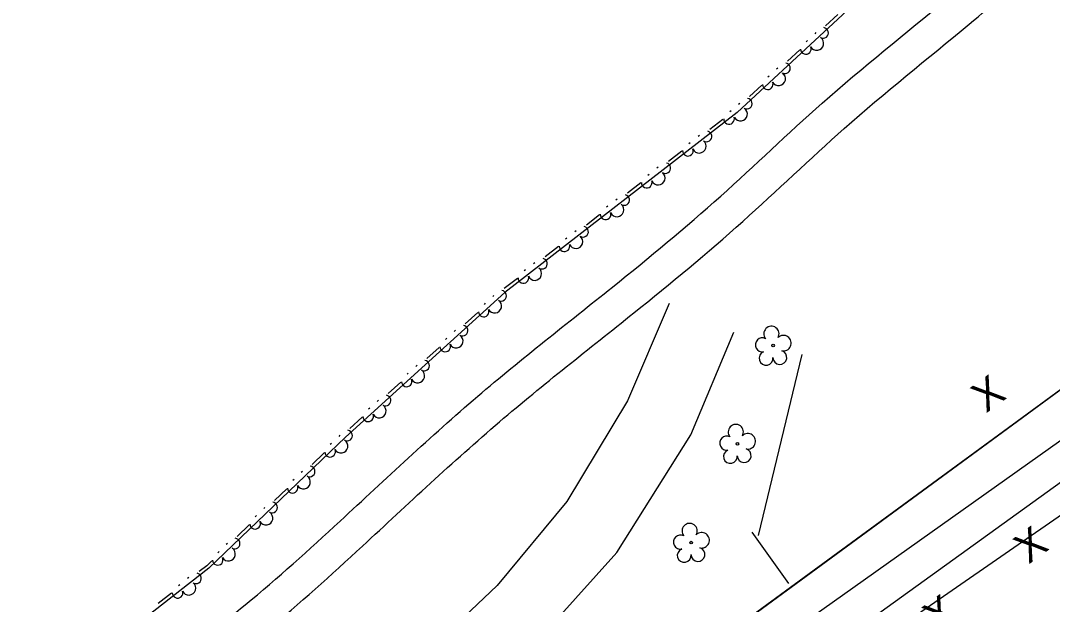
# Model space of a CAD drawing. Extents: x 1577032 to 1581865, y 611492 to 615011.
# Drawn here: x 1580788.7 to 1581041, y 614245.5 to 614388.2 of the extents above; entities that cross this region are included whole.
import ezdxf

# ---------------------------------------------------------------- set-up
doc = ezdxf.new("R2010")
doc.units = 0
for name, color, linetype in [('Exist Other Culture Fence Line', 7, 'Continuous'), ('Exist Right of Way Line', 7, 'Continuous'), ('Exist Roads Soil', 7, 'Continuous'), ('Exist Utilities Telephone UG FO SUE LOS B', 7, 'Continuous'), ('Exist Utilities Water UG Line SUE LOS B', 7, 'Continuous'), ('Exist Vegetation Tree CELL', 7, 'Continuous'), ('Old_Level_11', 7, 'Continuous'), ('Scratch_Level_4', 7, 'Continuous')]:
    doc.layers.add(name, color=color, linetype=linetype)

msp = doc.modelspace()

# ---------------------------------------------------------------- linework, layer by layer
at = {"layer": 'Exist Other Culture Fence Line'}
for p, q in [((1580969.09, 614262.33), (1580979.76, 614306.58)), ((1580969.09, 614262.33), (1580979.76, 614306.58)), ((1580976.57, 614250.53), (1580967.6, 614263.11)), ((1580976.57, 614250.53), (1580967.6, 614263.11))]:
    msp.add_line(p, q, dxfattribs=at)
for points in [[(1580843.54, 614151.95), (1580914.31, 614203.63), (1580981.96, 614253.3), (1581053.56, 614305.78), (1581115.1, 614350.96), (1581178.97, 614397.65), (1581213.26, 614422.92), (1581213.95, 614443.21), (1581207.27, 614448.89), (1581139.47, 614504.86)], [(1580843.54, 614151.95), (1581213.26, 614422.92), (1581213.95, 614443.21), (1581207.27, 614448.89), (1581139.47, 614504.86)], [(1580843.54, 614151.95), (1580914.31, 614203.63), (1580981.96, 614253.3), (1581053.56, 614305.78), (1581115.1, 614350.96), (1581178.97, 614397.65), (1581213.26, 614422.92), (1581213.95, 614443.21), (1581207.27, 614448.89)]]:
    msp.add_lwpolyline(points, dxfattribs=at)
at = {"layer": 'Exist Right of Way Line'}
msp.add_lwpolyline([(1580350.49, 613793.9), (1581560.23, 614652.99)], dxfattribs=at)
at = {"layer": 'Exist Roads Soil'}
for points in [[(1580947.25, 614319.05), (1580937.11, 614295.28), (1580922.28, 614270.62), (1580905.22, 614250.08), (1580885.95, 614231.74), (1580859.86, 614211.65), (1580836.93, 614193.69), (1580817.4, 614174.23), (1580801.52, 614151.03), (1580795.8, 614133.68), (1580792.46, 614114.3), (1580794.72, 614096.94), (1580801.59, 614080.9), (1580804.43, 614074.94), (1580805.4, 614069.46)], [(1580947.25, 614319.05), (1580937.11, 614295.28), (1580922.28, 614270.62), (1580905.22, 614250.08), (1580885.95, 614231.74), (1580859.86, 614211.65), (1580836.93, 614193.69), (1580817.4, 614174.23), (1580801.52, 614151.03), (1580795.8, 614133.68), (1580792.46, 614114.3), (1580794.72, 614096.94), (1580801.59, 614080.9), (1580804.43, 614074.94), (1580805.4, 614069.46)], [(1580842.62, 614097.61), (1580834.78, 614104.9), (1580827.64, 614117.28), (1580827.01, 614130.94), (1580831.8, 614152.77), (1580846.82, 614176.16), (1580880.36, 614204.32), (1580909.22, 614230.04), (1580934.52, 614258.19), (1580952.56, 614286.96), (1580963.08, 614312)], [(1580842.62, 614097.61), (1580834.78, 614104.9), (1580827.64, 614117.28), (1580827.01, 614130.94), (1580831.8, 614152.77), (1580846.82, 614176.16), (1580880.36, 614204.32), (1580909.22, 614230.04), (1580934.52, 614258.19), (1580952.56, 614286.96), (1580963.08, 614312)]]:
    msp.add_lwpolyline(points, dxfattribs=at)
at = {"layer": 'Exist Utilities Telephone UG FO SUE LOS B'}
msp.add_lwpolyline([(1580541.92, 613911.34), (1580565.99, 613928.5), (1580575.38, 613936.54), (1580607.26, 613958.8), (1580640.94, 613978.44), (1580673.15, 613998.31), (1580719.17, 614030.82), (1580788.35, 614087.85), (1580845.17, 614134.91), (1580876.01, 614149.96), (1580927.93, 614187.6), (1580984.72, 614225.98), (1580987.35, 614228.77), (1581072.57, 614287.71), (1581106.01, 614311.08), (1581124.14, 614323.41), (1581136.77, 614334.4), (1581140.56, 614340.68), (1581160.35, 614356.31), (1581239.56, 614412.21)], dxfattribs=at)
at = {"layer": 'Exist Utilities Water UG Line SUE LOS B'}
msp.add_line((1580981.18, 614230.87), (1581064.77, 614291.07), dxfattribs=at)
at = {"layer": 'Exist Vegetation Tree CELL'}
for p, q in [((1580972.67, 614308.76), (1580972.67, 614308.76)), ((1580963.95, 614284.75), (1580963.95, 614284.75)), ((1580952.67, 614260.56), (1580952.67, 614260.56))]:
    msp.add_line(p, q, dxfattribs=at)
for centre in [(1580972.67, 614308.76), (1580963.95, 614284.75), (1580952.67, 614260.56)]:
    msp.add_circle(centre, 0.326, dxfattribs=at)
for centre, radius, start, end in [((1580972.28, 614311.63), 1.86, 330.1651, 219.7134), ((1580970.06, 614308.91), 1.73, 62.6636, 279.3457), ((1580975.22, 614309.35), 1.9, 257.1011, 134.1999), ((1580970.96, 614305.64), 1.69, 111.5671, 6.231), ((1580974.34, 614305.86), 1.7, 181.2822, 74.56), ((1580963.57, 614287.63), 1.86, 330.1651, 219.7134), ((1580961.35, 614284.91), 1.73, 62.6636, 279.3457), ((1580966.5, 614285.34), 1.9, 257.1011, 134.1999), ((1580962.25, 614281.63), 1.69, 111.5671, 6.231), ((1580965.62, 614281.85), 1.7, 181.2822, 74.56), ((1580952.28, 614263.43), 1.86, 330.1651, 219.7134), ((1580950.06, 614260.71), 1.73, 62.6636, 279.3457), ((1580955.22, 614261.15), 1.9, 257.1011, 134.1999), ((1580950.96, 614257.44), 1.69, 111.5671, 6.231), ((1580954.34, 614257.66), 1.7, 181.2822, 74.56)]:
    msp.add_arc(centre, radius, start, end, dxfattribs=at)
at = {"layer": 'Old_Level_11'}
for points in [[(1581076.08, 614559.89), (1581088.52, 614547.83), (1581100.64, 614534.14), (1581112.37, 614518.46), (1581110.88, 614504.93), (1581098.08, 614486.05), (1581066.09, 614457.4), (1581031.44, 614426.4), (1580993.03, 614392.77), (1580963.93, 614365.74), (1580907.09, 614321.77), (1580868.13, 614286.39), (1580834.77, 614254.31), (1580805.23, 614231.21)], [(1580988.55, 614389.73), (1580985.54, 614386.94)], [(1580983.16, 614385.29), (1580982.86, 614385.01)], [(1580981.06, 614383.33), (1580980.76, 614383.06)], [(1580979.23, 614381.08), (1580976.23, 614378.29)], [(1580973.85, 614376.64), (1580973.55, 614376.36)], [(1580969.92, 614372.43), (1580966.91, 614369.64)], [(1580971.74, 614374.68), (1580971.44, 614374.4)], [(1580964.53, 614367.98), (1580964.23, 614367.7)], [(1580962.46, 614366.16), (1580962.14, 614365.91)], [(1580960.44, 614364.08), (1580957.2, 614361.57)], [(1580954.67, 614360.14), (1580954.35, 614359.89)], [(1580952.4, 614358.38), (1580952.08, 614358.13)], [(1580950.38, 614356.3), (1580947.14, 614353.79)], [(1580944.62, 614352.36), (1580944.3, 614352.11)], [(1580942.35, 614350.61), (1580942.03, 614350.36)], [(1580940.33, 614348.52), (1580937.09, 614346.02)], [(1580934.56, 614344.58), (1580934.24, 614344.33)], [(1580932.29, 614342.83), (1580931.97, 614342.58)], [(1580930.27, 614340.75), (1580927.03, 614338.24)], [(1580922.24, 614335.05), (1580921.91, 614334.8)], [(1580924.51, 614336.8), (1580924.18, 614336.55)], [(1580920.22, 614332.97), (1580916.97, 614330.46)], [(1580912.18, 614327.27), (1580911.86, 614327.02)], [(1580914.45, 614329.02), (1580914.13, 614328.77)], [(1580910.16, 614325.19), (1580906.92, 614322.68)], [(1580904.45, 614321.03), (1580904.14, 614320.76)], [(1580900.47, 614316.87), (1580897.44, 614314.11)], [(1580902.32, 614319.1), (1580902.02, 614318.83)], [(1580895.04, 614312.49), (1580894.73, 614312.21)], [(1580892.91, 614310.56), (1580892.61, 614310.28)], [(1580891.06, 614308.32), (1580888.03, 614305.57)], [(1580883.5, 614302.01), (1580883.2, 614301.73)], [(1580885.63, 614303.94), (1580885.32, 614303.66)], [(1580881.65, 614299.78), (1580878.62, 614297.02)], [(1580876.21, 614295.39), (1580875.91, 614295.12)], [(1580874.09, 614293.46), (1580873.79, 614293.19)], [(1580872.24, 614291.23), (1580869.2, 614288.47)], [(1580866.79, 614286.81), (1580866.5, 614286.52)], [(1580864.72, 614284.82), (1580864.43, 614284.53)], [(1580862.94, 614282.53), (1580859.98, 614279.69)], [(1580857.63, 614278), (1580857.33, 614277.71)], [(1580855.56, 614276.01), (1580855.26, 614275.72)], [(1580853.77, 614273.72), (1580850.81, 614270.88)], [(1580848.46, 614269.19), (1580848.17, 614268.9)], [(1580846.39, 614267.2), (1580846.1, 614266.91)], [(1580844.61, 614264.91), (1580841.65, 614262.07)], [(1580839.29, 614260.37), (1580839, 614260.09)], [(1580837.23, 614258.39), (1580836.93, 614258.1)], [(1580835.44, 614256.1), (1580834.23, 614254.93), (1580832.39, 614253.5)], [(1580829.88, 614252.05), (1580829.55, 614251.8)], [(1580827.61, 614250.28), (1580827.29, 614250.03)], [(1580825.61, 614248.19), (1580822.38, 614245.66)]]:
    msp.add_lwpolyline(points, dxfattribs=at)
for centre, radius, start, end in [((1580984.9, 614385.22), 1.3, 241.3186, 82.1152), ((1580983.36, 614382.67), 1.69, 208.8474, 56.9199), ((1580980.69, 614381.32), 1.3, 183.6522, 24.4487), ((1580975.59, 614376.57), 1.3, 241.3186, 82.1152), ((1580974.04, 614374.02), 1.69, 208.8474, 56.9199), ((1580971.38, 614372.66), 1.3, 183.6522, 24.4487), ((1580966.27, 614367.92), 1.3, 241.3186, 82.1152), ((1580964.72, 614365.37), 1.69, 208.8474, 56.9199), ((1580961.92, 614364.19), 1.3, 178.495, 19.2916), ((1580956.4, 614359.92), 1.3, 236.1615, 76.9581), ((1580954.63, 614357.52), 1.69, 203.6903, 51.7628), ((1580951.86, 614356.41), 1.3, 178.495, 19.2916), ((1580946.35, 614352.14), 1.3, 236.1615, 76.9581), ((1580944.58, 614349.74), 1.69, 203.6903, 51.7628), ((1580941.8, 614348.63), 1.3, 178.495, 19.2916), ((1580936.29, 614344.36), 1.3, 236.1615, 76.9581), ((1580934.52, 614341.96), 1.69, 203.6903, 51.7628), ((1580931.75, 614340.85), 1.3, 178.495, 19.2916), ((1580926.23, 614336.58), 1.3, 236.1615, 76.9581), ((1580924.47, 614334.18), 1.69, 203.6903, 51.7628), ((1580921.69, 614333.07), 1.3, 178.495, 19.2916), ((1580916.18, 614328.8), 1.3, 236.1615, 76.9581), ((1580914.41, 614326.4), 1.69, 203.6903, 51.7628), ((1580911.64, 614325.29), 1.3, 178.495, 19.2916), ((1580906.19, 614320.95), 1.3, 240.6812, 81.4778), ((1580904.61, 614318.41), 1.69, 208.21, 56.2825), ((1580901.94, 614317.09), 1.3, 183.0147, 23.8113), ((1580896.77, 614312.4), 1.3, 240.6812, 81.4778), ((1580895.2, 614309.87), 1.69, 208.21, 56.2825), ((1580892.52, 614308.54), 1.3, 183.0147, 23.8113), ((1580887.36, 614303.86), 1.3, 240.6812, 81.4778), ((1580885.79, 614301.32), 1.69, 208.21, 56.2825), ((1580883.11, 614300), 1.3, 183.0147, 23.8113), ((1580877.95, 614295.31), 1.3, 240.6812, 81.4778), ((1580876.38, 614292.77), 1.69, 208.21, 56.2825), ((1580873.7, 614291.45), 1.3, 183.0147, 23.8113), ((1580868.54, 614286.76), 1.3, 240.6812, 81.4778), ((1580867.03, 614284.19), 1.69, 209.8356, 57.9081), ((1580864.39, 614282.79), 1.3, 184.6403, 25.4369), ((1580859.37, 614277.96), 1.3, 242.3068, 83.1034), ((1580857.86, 614275.38), 1.69, 209.8356, 57.9081), ((1580855.23, 614273.98), 1.3, 184.6403, 25.4369), ((1580850.2, 614269.15), 1.3, 242.3068, 83.1034), ((1580848.7, 614266.57), 1.69, 209.8356, 57.9081), ((1580846.06, 614265.17), 1.3, 184.6403, 25.4369), ((1580841.04, 614260.34), 1.3, 242.3068, 83.1034), ((1580839.53, 614257.76), 1.69, 209.8356, 57.9081), ((1580836.9, 614256.36), 1.3, 184.6403, 25.4369), ((1580831.6, 614251.84), 1.3, 236.4744, 77.2709), ((1580827.08, 614248.3), 1.3, 178.8079, 19.6045), ((1580829.85, 614249.42), 1.69, 204.0032, 52.0757)]:
    msp.add_arc(centre, radius, start, end, dxfattribs=at)
at = {"layer": 'Scratch_Level_4'}
for points in [[(1580810.22, 614218.65), (1580825.05, 614230.72), (1580843.62, 614245.36), (1580866.82, 614265.83), (1580900.47, 614296.36), (1580933.43, 614323.08), (1580959.89, 614345.31), (1580984.67, 614368.02), (1581015.29, 614393.59), (1581049.92, 614423.64), (1581082.64, 614453.16), (1581106.95, 614476.82), (1581123.61, 614498.18), (1581131.45, 614509.84)], [(1580815.44, 614212.32), (1580830.18, 614224.32), (1580848.88, 614239.06), (1580872.29, 614259.72), (1580905.81, 614290.13), (1580938.65, 614316.75), (1580965.3, 614339.14), (1580990.07, 614361.84), (1581020.61, 614387.35), (1581055.35, 614417.49), (1581088.25, 614447.18), (1581113.07, 614471.33), (1581130.26, 614493.37), (1581138.39, 614505.46)]]:
    msp.add_spline(points, degree=3, dxfattribs=at)

# ---------------------------------------------------------------- texts
at = {"layer": 'Exist Vegetation Tree CELL'}
for p in [(1581024.73, 614292.14), (1581035.13, 614255.17), (1581012.88, 614238.44)]:
    msp.add_text('X', height=7.38, rotation=36.0651, dxfattribs=at).set_placement(p)

doc.saveas('drawing.dxf')
